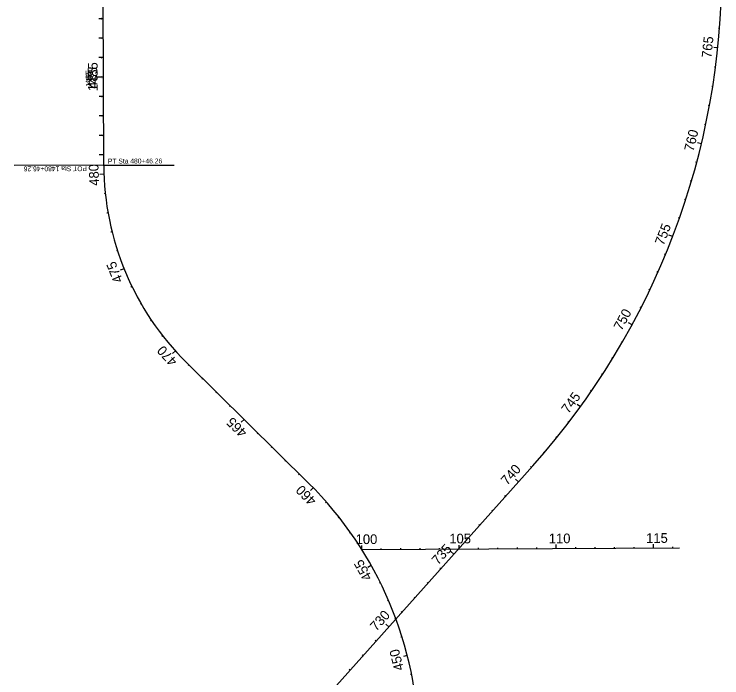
# Model space of a CAD drawing. Extents: x 448091 to 665917, y 1461380 to 1587607.
# Drawn here: x 449623 to 453263, y 1499776 to 1503190 of the extents above; entities that cross this region are included whole.
import ezdxf

# ---------------------------------------------------------------- set-up
doc = ezdxf.new("R2010")
doc.units = 0
for name, color, linetype in [('AttenuatorTM', 7, 'Continuous'), ('ATVHP', 7, 'Continuous'), ('Default', 7, 'Continuous'), ('TextShtNo', 7, 'Continuous'), ('TextTitle', 7, 'Continuous')]:
    doc.layers.add(name, color=color, linetype=linetype)

msp = doc.modelspace()

# ---------------------------------------------------------------- linework, layer by layer
at = {"layer": 'AttenuatorTM'}
for p, q in [((450081.3, 1502413.1), (449622.9, 1502411.8)), ((450086.3, 1502413.1), (450446.1, 1502414.1))]:
    msp.add_line(p, q, dxfattribs=at)
msp.add_circle((450083.8, 1502413.1), 2.5, dxfattribs=at)
at = {"layer": 'ATVHP'}
for p, q in [((450083.8, 1502413.1), (450080.5, 1503586.2)), ((450081.7, 1503166.8), (450075.9, 1503166.8)), ((450081.9, 1503066.8), (450076.2, 1503066.8)), ((450082.2, 1502966.8), (450076.5, 1502966.8)), ((450082.5, 1502866.8), (450061.8, 1502866.8)), ((450082.8, 1502766.8), (450077, 1502766.8)), ((450083.1, 1502666.8), (450077.3, 1502666.8)), ((450083.4, 1502566.8), (450077.6, 1502566.8)), ((450083.6, 1502466.8), (450077.9, 1502466.8))]:
    msp.add_line(p, q, dxfattribs=at)
at = {"layer": 'Default'}
for p, q in [((450081.7, 1503166.8), (450058.7, 1503166.7)), ((450081.7, 1503166.8), (450058.7, 1503166.7)), ((450081.7, 1503166.8), (450077.4, 1503166.8)), ((450081.7, 1503166.8), (450077.4, 1503166.8)), ((450081.9, 1503066.8), (450058.9, 1503066.7)), ((450081.9, 1503066.8), (450058.9, 1503066.7)), ((450081.9, 1503066.8), (450077.6, 1503066.8)), ((450081.9, 1503066.8), (450077.6, 1503066.8)), ((450082.2, 1502966.8), (450059.2, 1502966.7)), ((450082.2, 1502966.8), (450059.2, 1502966.7)), ((450082.2, 1502966.8), (450077.9, 1502966.8)), ((450082.2, 1502966.8), (450077.9, 1502966.8)), ((450082.5, 1502866.8), (450039.5, 1502866.7)), ((450082.5, 1502866.8), (450039.5, 1502866.7)), ((450082.5, 1502866.8), (450078.2, 1502866.8)), ((450082.5, 1502866.8), (450078.2, 1502866.8)), ((450082.8, 1502766.8), (450059.8, 1502766.7)), ((450082.8, 1502766.8), (450059.8, 1502766.7)), ((450082.8, 1502766.8), (450078.5, 1502766.8)), ((450082.8, 1502766.8), (450078.5, 1502766.8)), ((450083.1, 1502666.8), (450060.1, 1502666.7)), ((450083.1, 1502666.8), (450060.1, 1502666.7)), ((450083.1, 1502666.8), (450078.8, 1502666.8)), ((450083.1, 1502666.8), (450078.8, 1502666.8)), ((450083.4, 1502566.8), (450060.4, 1502566.7)), ((450083.4, 1502566.8), (450060.4, 1502566.7)), ((450083.4, 1502566.8), (450079.1, 1502566.8)), ((450083.4, 1502566.8), (450079.1, 1502566.8)), ((450083.6, 1502466.8), (450060.6, 1502466.7)), ((450083.6, 1502466.8), (450060.6, 1502466.7)), ((450083.6, 1502466.8), (450079.3, 1502466.8)), ((450083.6, 1502466.8), (450079.3, 1502466.8))]:
    msp.add_line(p, q, dxfattribs=at)
at = {"layer": 'TextShtNo'}
for p, q in [((450083.8, 1502413.1), (450080.5, 1503586.2)), ((450083.8, 1502413.1), (450080.5, 1503586.2)), ((451137, 1500777.7), (450509.1, 1501398.6)), ((450940.8, 1499356), (452291.2, 1500867.2)), ((451411.3, 1500435.9), (453045.5, 1500444.3))]:
    msp.add_line(p, q, dxfattribs=at)
for centre, radius, start, end in [((449442.9, 1503412.3), 3819.7, 318.2164, 0.2656), ((451516.2, 1502417.1), 1432.4, 180.1629, 225.3257), ((449794.2, 1499419.6), 1909.9, 0.4508, 45.3257)]:
    msp.add_arc(centre, radius, start, end, dxfattribs=at)
at = {"layer": 'TextTitle'}
for p, q in [((450081.7, 1503166.8), (450071.7, 1503166.8)), ((450081.7, 1503166.8), (450075.9, 1503166.8)), ((453251.1, 1503115.8), (453245.4, 1503116.2)), ((450081.9, 1503066.8), (450071.9, 1503066.8)), ((450081.9, 1503066.8), (450076.2, 1503066.8)), ((453242.1, 1503016.2), (453221.4, 1503018.3)), ((450082.2, 1502966.8), (450072.2, 1502966.8)), ((450082.2, 1502966.8), (450076.5, 1502966.8)), ((453230.4, 1502916.9), (453224.7, 1502917.6)), ((450082.5, 1502866.8), (450071.8, 1502866.8)), ((450082.5, 1502866.8), (450071.8, 1502866.8)), ((453216.1, 1502817.9), (453210.4, 1502818.8)), ((450082.8, 1502766.8), (450077, 1502766.8)), ((450082.8, 1502766.8), (450077, 1502766.8)), ((453199.3, 1502719.3), (453193.6, 1502720.4)), ((450083.1, 1502666.8), (450077.3, 1502666.8)), ((450083.1, 1502666.8), (450077.3, 1502666.8)), ((453179.8, 1502621.2), (453174.2, 1502622.4)), ((450083.4, 1502566.8), (450077.6, 1502566.8)), ((450083.4, 1502566.8), (450077.6, 1502566.8)), ((453157.8, 1502523.7), (453137.7, 1502528.5)), ((450083.6, 1502466.8), (450077.9, 1502466.8)), ((450083.6, 1502466.8), (450077.9, 1502466.8)), ((453133.3, 1502426.8), (453127.8, 1502428.2)), ((450084.7, 1502366.8), (450063.9, 1502366.1)), ((453106.2, 1502330.5), (453100.7, 1502332.1)), ((450091.7, 1502267.1), (450086, 1502266.5)), ((453076.7, 1502235), (453071.2, 1502236.7)), ((450105.6, 1502168.1), (450100, 1502167.1)), ((453044.6, 1502140.2), (453039.2, 1502142.2)), ((450126.4, 1502070.3), (450120.8, 1502068.9)), ((453010.1, 1502046.4), (452990.7, 1502053.8)), ((450154, 1501974.2), (450148.5, 1501972.4)), ((452973.1, 1501953.5), (452967.8, 1501955.7)), ((450188.2, 1501880.3), (450169, 1501872.5)), ((452933.7, 1501861.6), (452928.4, 1501863.9)), ((450228.9, 1501788.9), (450223.7, 1501786.4)), ((452891.9, 1501770.7), (452886.7, 1501773.2)), ((450275.9, 1501700.7), (450270.9, 1501697.8)), ((452847.8, 1501681), (452842.6, 1501683.6)), ((450328.9, 1501615.9), (450324.1, 1501612.7)), ((452801.3, 1501592.5), (452783, 1501602.4)), ((450387.7, 1501535), (450383.1, 1501531.5)), ((452752.5, 1501505.2), (452747.5, 1501508.1)), ((450451.9, 1501458.4), (450436.5, 1501444.6)), ((452701.4, 1501419.2), (452696.5, 1501422.2)), ((450521.3, 1501386.5), (450517.3, 1501382.4)), ((450592.4, 1501316.2), (450588.4, 1501312.1)), ((452648.1, 1501334.6), (452643.3, 1501337.7)), ((450663.6, 1501245.8), (450659.5, 1501241.8)), ((452592.6, 1501251.4), (452587.9, 1501254.7)), ((450734.7, 1501175.5), (450730.6, 1501171.5)), ((452535, 1501169.7), (452518.2, 1501181.9)), ((450805.8, 1501105.2), (450791.2, 1501090.5)), ((452475.2, 1501089.5), (452470.7, 1501093)), ((450876.9, 1501034.9), (450872.8, 1501030.8)), ((452413.4, 1501011), (452408.9, 1501014.6)), ((450948, 1500964.6), (450944, 1500960.5)), ((452349.5, 1500934), (452345.1, 1500937.7)), ((451019.1, 1500894.3), (451015.1, 1500890.2)), ((452283.7, 1500858.8), (452279.4, 1500862.6)), ((451090.2, 1500824), (451086.2, 1500819.9)), ((452217, 1500784.2), (452201.5, 1500798)), ((451161.1, 1500753.5), (451146.3, 1500739)), ((452150.4, 1500709.6), (452146.1, 1500713.5)), ((451229.1, 1500680.1), (451224.7, 1500676.3)), ((452083.8, 1500635.1), (452079.5, 1500638.9)), ((451293.1, 1500603.3), (451288.5, 1500599.7)), ((452017.1, 1500560.5), (452012.8, 1500564.3)), ((451353, 1500523.2), (451348.3, 1500519.9)), ((451950.5, 1500485.9), (451946.2, 1500489.8)), ((451411.3, 1500435.9), (451411.2, 1500456.6)), ((451511.3, 1500436.4), (451511.2, 1500442.1)), ((451611.3, 1500436.9), (451611.2, 1500442.7)), ((451711.3, 1500437.4), (451711.2, 1500443.2)), ((451811.3, 1500437.9), (451811.2, 1500443.7)), ((451911.3, 1500438.5), (451911.2, 1500459.2)), ((452011.3, 1500439), (452011.2, 1500444.7)), ((452111.3, 1500439.5), (452111.2, 1500445.2)), ((452211.3, 1500440), (452211.2, 1500445.8)), ((452311.3, 1500440.5), (452311.2, 1500446.3)), ((452411.3, 1500441.1), (452411.1, 1500461.8)), ((452511.3, 1500441.6), (452511.2, 1500447.3)), ((452611.3, 1500442.1), (452611.2, 1500447.8)), ((452711.3, 1500442.6), (452711.2, 1500448.4)), ((452811.2, 1500443.1), (452811.2, 1500448.9)), ((452911.2, 1500443.6), (452911.1, 1500464.4)), ((453011.2, 1500444.2), (453011.2, 1500449.9)), ((451408.6, 1500440.1), (451403.7, 1500437.1)), ((451883.9, 1500411.4), (451868.4, 1500425.2)), ((451459.8, 1500354.3), (451441.7, 1500344.1)), ((451817.2, 1500336.8), (451812.9, 1500340.6)), ((451506.4, 1500265.8), (451501.3, 1500263.3)), ((451750.6, 1500262.2), (451746.3, 1500266.1)), ((451684, 1500187.7), (451679.7, 1500191.5)), ((451548.3, 1500175), (451543.1, 1500172.8)), ((451617.3, 1500113.1), (451613, 1500116.9)), ((451585.5, 1500082.2), (451580.1, 1500080.2)), ((451550.7, 1500038.5), (451535.2, 1500052.4)), ((451617.7, 1499987.5), (451612.2, 1499985.8)), ((451484.1, 1499964), (451479.8, 1499967.8)), ((451417.4, 1499889.4), (451413.1, 1499893.2)), ((451644.9, 1499891.3), (451624.8, 1499886.2)), ((451350.8, 1499814.8), (451346.5, 1499818.7)), ((451667.1, 1499793.8), (451661.4, 1499792.7))]:
    msp.add_line(p, q, dxfattribs=at)

# ---------------------------------------------------------------- texts
at = {"layer": 'AttenuatorTM'}
for s, rotation, p in [('PT Sta 480+46.26', 0.1629, (450105.2, 1502421.7)), ('POT Sta 1480+46.26', 180.1629, (449997.4, 1502407.7))]:
    msp.add_text(s, height=25, rotation=rotation, dxfattribs=at).set_placement(p)
at = {"layer": 'ATVHP'}
msp.add_text('485', height=50, rotation=90.1629, dxfattribs=at).set_placement((450051.4, 1502806.4))
at = {"layer": 'Default'}
for s, height, p in [('1488', 4, (450074.9, 1503159.7)), ('488', 4, (450074.9, 1503161.7)), ('1487', 4, (450075.2, 1503059.7)), ('487', 4, (450075.2, 1503061.6)), ('1486', 4, (450075.4, 1502959.6)), ('486', 4, (450075.4, 1502961.6)), ('1485', 28, (450019.7, 1502816.7)), ('485', 28, (450019.6, 1502830.6)), ('1485', 4, (450075.7, 1502859.7)), ('485', 4, (450075.7, 1502861.6)), ('1484', 4, (450076, 1502759.7)), ('484', 4, (450076, 1502761.7)), ('1483', 4, (450076.3, 1502659.7)), ('483', 4, (450076.3, 1502661.7)), ('1482', 4, (450076.6, 1502559.7)), ('482', 4, (450076.6, 1502561.7)), ('1481', 4, (450076.9, 1502460.3)), ('481', 4, (450076.9, 1502462.3))]:
    msp.add_text(s, height=height, rotation=90.1629, dxfattribs=at).set_placement(p)
at = {"layer": 'TextTitle'}
for s, rotation, p in [('765', 84.047, (453208.3, 1502962.8)), ('1485', 90.1629, (450052.8, 1502794.1)), ('760', 76.547, (453116.7, 1502480.9)), ('480', 92.0133, (450060.1, 1502308.3)), ('755', 69.047, (452962.9, 1501997)), ('475', 112.0134, (450183.5, 1501819.6)), ('750', 61.547, (452747.1, 1501558.5)), ('470', 132.0134, (450465.4, 1501406.6)), ('745', 54.047, (452473.6, 1501131.9)), ('465', 135.3257, (450824.8, 1501042.5)), ('740', 48.2164, (452158.5, 1500763.5)), ('460', 134.2996, (451180.8, 1500691.7)), ('100', 0.2971, (451379.3, 1500463.8)), ('105', 0.2971, (451861, 1500467.1)), ('110', 0.2971, (452372.7, 1500467.9)), ('115', 0.2971, (452873.3, 1500469.8)), ('735', 48.2164, (451803, 1500353.2)), ('455', 119.2996, (451465.8, 1500292.6)), ('730', 48.2164, (451485.6, 1500012.4)), ('450', 104.2996, (451627.9, 1499819.6))]:
    msp.add_text(s, height=50, rotation=rotation, dxfattribs=at).set_placement(p)

doc.saveas('drawing.dxf')
